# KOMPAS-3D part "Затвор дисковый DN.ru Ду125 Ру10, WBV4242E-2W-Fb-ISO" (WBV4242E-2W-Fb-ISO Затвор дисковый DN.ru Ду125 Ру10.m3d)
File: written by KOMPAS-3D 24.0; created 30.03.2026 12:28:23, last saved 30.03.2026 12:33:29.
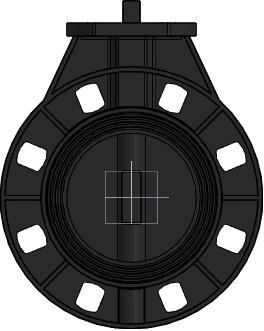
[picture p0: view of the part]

Document properties: Автор: R2D2; Полное имя файла: WBV4242E-2W-Fb-ISO Затвор дисковый DN.ru Ду125 Ру10.cdw

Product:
- Part/product: Затвор дисковый DN.ru Ду125 Ру10  | designation WBV4242E-2W-Fb-ISO
    Масса: 3.26
    Раздел спецификации: Прочие изделия
    Форматы листов документа: A2
    Примечание: D050-81208

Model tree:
1. Операция без истории:1

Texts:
  WBV4242E-2W-Fb-ISO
